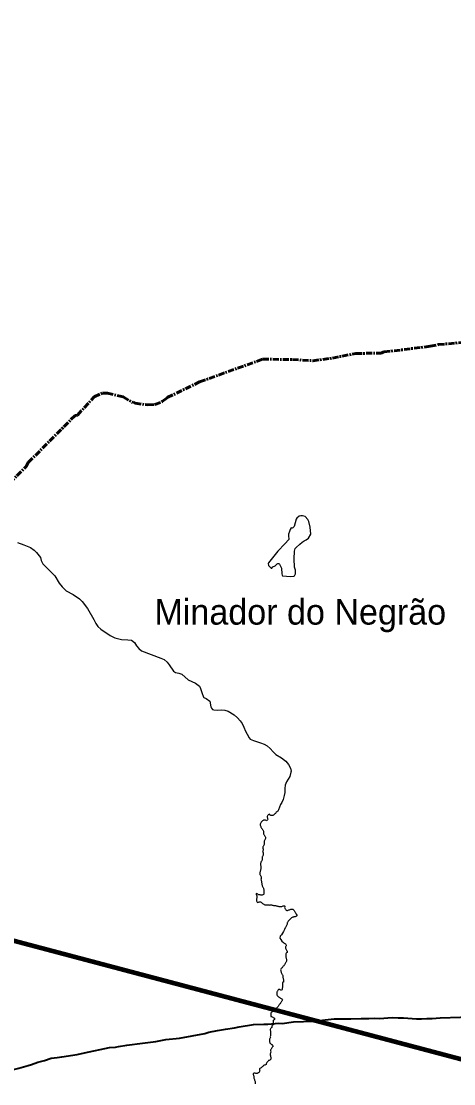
# Model space of a CAD drawing. Extents: x 553962 to 842807, y 8883888 to 9032388.
# Drawn here: x 729266 to 737754, y 8959904 to 8980756 of the extents above; entities that cross this region are included whole.
import ezdxf

# ---------------------------------------------------------------- set-up
doc = ezdxf.new("R2010")
doc.units = 0
doc.header["$LTSCALE"] = 20
doc.linetypes.add('LONG_DASH_SHORT_DASH', pattern=[9.9, 6, -1.2, 1.5, -1.2])
for name, color, linetype, lineweight in [('12', 7, 'Continuous', 25), ('21', 7, 'Continuous', 25), ('24', 7, 'Continuous', 25), ('7', 7, 'LONG_DASH_SHORT_DASH', 60), ('9', 7, 'Continuous', 90)]:
    doc.layers.add(name, color=color, linetype=linetype, lineweight=lineweight)
doc.layers.add('41', color=7, linetype='Continuous')

msp = doc.modelspace()

# ---------------------------------------------------------------- linework, layer by layer
at = {"layer": '12', "lineweight": 40}
for points in [[(734025.23, 8961072.32), (734102.39, 8961075.4), (734319.41, 8961091.81), (734386.94, 8961088.99), (734610.49, 8961116.12), (735000.79, 8961131.4), (735406.19, 8961178.84), (735620.81, 8961178.72)], [(735620.81, 8961178.72), (735731.47, 8961178.65), (735939.14, 8961184.67), (736086.36, 8961182.84), (736197.06, 8961189.1), (736304, 8961187.6), (736462.5, 8961200.24), (736543.42, 8961202.13), (736665.09, 8961195.82), (736768.25, 8961197.31), (737022.4, 8961176.73), (737121.76, 8961176.47), (737224.94, 8961184.42), (737328.09, 8961184.85), (737486.64, 8961197.57), (738285.52, 8961221)], [(731644.16, 8960700.61), (731907.06, 8960733.7), (732104.59, 8960770.61), (732374.96, 8960800.82), (732870.21, 8960888.22), (732949.72, 8960916.31), (733119.64, 8960947.44)], [(733119.64, 8960947.44), (733273.34, 8960975.61), (733450.74, 8961003.08), (733541.83, 8961022.02), (733826.97, 8961064.42), (734025.23, 8961072.32)], [(727488.2, 8960282.3), (728636.39, 8960199.63), (728903.43, 8960161.82), (729137.06, 8960189.26), (729219.73, 8960208.11), (729400.96, 8960258.8), (729465.41, 8960280.38), (729590.56, 8960330.01), (729719.37, 8960362.95), (729852.47, 8960406.02), (729968.99, 8960418.16), (730064.27, 8960434.81), (730362.78, 8960475.91), (730505.92, 8960510.9), (731000.54, 8960614.44), (731116.07, 8960622.55), (731172.08, 8960636.38), (731339.7, 8960662.29), (731644.16, 8960700.61)]]:
    msp.add_lwpolyline(points, dxfattribs=at)
at = {"layer": '21'}
for points in [[(734441.25, 8970498.94), (734303.77, 8970355.74), (734116.51, 8970129.87), (734113.07, 8970114.68), (734119.43, 8970075.48), (734145.25, 8970051.16), (734168.88, 8970019.47), (734181.41, 8970021.52), (734206.5, 8970050.81), (734247.17, 8970065.81), (734290.42, 8970107.38), (734303.52, 8970111.68), (734321.81, 8970111.11), (734333.6, 8970097.89), (734374.96, 8970020.47), (734381.73, 8969909.65), (734389.66, 8969884.17), (734396.24, 8969874.79), (734551.18, 8969860.5), (734613.74, 8969866.7), (734627.41, 8969872.56), (734648.28, 8969912.44), (734649.57, 8969980.8), (734634.29, 8970019.7), (734630.75, 8970039.72), (734623.83, 8970208.99), (734629.39, 8970357.23), (734643.75, 8970405.73), (734658.93, 8970427.23), (734730.63, 8970496.32), (734782.06, 8970530.81), (734817.51, 8970561.34), (734855.16, 8970579.8), (734904.19, 8970611.74), (734951.1, 8970691.29), (734935.85, 8970827.66), (734908.42, 8970936.35), (734891.26, 8970974.5), (734841.32, 8971037.05), (734782.72, 8971051.2)], [(734782.72, 8971051.2), (734756.15, 8971050.77), (734720.75, 8971040.11), (734672.04, 8971001.37), (734663.35, 8970981.58), (734624.87, 8970837.4), (734592.12, 8970806.26), (734562.44, 8970812.01), (734543.57, 8970783.68), (734532.01, 8970740.49), (734512.55, 8970689.17), (734508.82, 8970650.11), (734519.5, 8970599.79), (734514.75, 8970584.31), (734441.25, 8970498.94)]]:
    msp.add_lwpolyline(points, dxfattribs=at)
at = {"layer": '24'}
for points in [[(729191.82, 8970527), (729315.43, 8970483.83), (729446.41, 8970430.03), (729519.73, 8970373.95), (729562.91, 8970331.72), (729643.81, 8970234.41), (729657.78, 8970174.07), (729686.56, 8970110.75), (729928.32, 8969870.5), (730012.38, 8969726.43), (730069.72, 8969653.94), (730149.15, 8969579.47), (730284.77, 8969503.88), (730411.96, 8969418.67), (730463.19, 8969367.61), (730567.65, 8969229.84), (730688.65, 8969016.48), (730730.28, 8968933.73), (730772.23, 8968877.43), (730829.84, 8968823.32), (731008.22, 8968703.56), (731105.33, 8968654.76), (731233.03, 8968624.61), (731360.63, 8968619.29), (731432.16, 8968607.51), (731490.37, 8968564.55), (731529.04, 8968498.91), (731571.99, 8968444.09), (731629.25, 8968401.55), (732006.06, 8968259.5), (732068.71, 8968231.38), (732130.1, 8968177.51), (732172.29, 8968124.3), (732254.14, 8968003.81), (732270.76, 8967986.03), (732292.33, 8967973.47), (732359.39, 8967962.26), (732419.13, 8967940.3), (732541.41, 8967832.4), (732686.56, 8967768.49), (732762.42, 8967705.47), (732787.2, 8967659.88), (732807.75, 8967584.85), (732842.44, 8967493.06), (732851.1, 8967484), (732892.33, 8967462.77), (732967.31, 8967414.94), (732985.96, 8967299.95), (732997.76, 8967278.09), (733022.77, 8967248.47), (733047.48, 8967241.38), (733120.28, 8967238.55), (733188.75, 8967243.53), (733264.7, 8967233.67), (733328.02, 8967214.7), (733447.65, 8967146.11), (733512.9, 8967086.79), (733564.47, 8967027.37), (733599.25, 8966975.33), (733599.25, 8966975.33), (733635.85, 8966903.53)], [(733635.85, 8966903.53), (733667.36, 8966823.62), (733697.18, 8966763.32), (733739.02, 8966694.9), (733760.67, 8966668.39), (733825.78, 8966637.78), (733959.02, 8966591.55), (734034.53, 8966569.68), (734094.57, 8966536.18), (734151.46, 8966484.99), (734209.19, 8966415.67), (734259.55, 8966363.68), (734370.9, 8966301.89), (734433.38, 8966256.02), (734458.56, 8966232.5), (734511.17, 8966171.09), (734552.02, 8966096.35), (734560.3, 8966041.1), (734559.63, 8966020.25), (734537.32, 8965930.66), (734471.1, 8965827.99), (734446.15, 8965764.37), (734439.47, 8965701.01), (734438.02, 8965620.35), (734427.42, 8965560.59), (734408.24, 8965484.42), (734379, 8965420.64), (734356.71, 8965384.15), (734317.42, 8965278.86)], [(734317.42, 8965278.86), (734316.73, 8965277.61), (734309.62, 8965266.03), (734300.35, 8965256.16), (734290.85, 8965247.98), (734280.02, 8965241.51), (734271, 8965232.36), (734262.08, 8965222.25), (734255.22, 8965210.79), (734245.95, 8965201.4), (734235.35, 8965192.38), (734225.24, 8965183.61), (734214.53, 8965176.77), (734203.35, 8965171.15), (734191.09, 8965168.98), (734176.5, 8965168.15), (734165.42, 8965170.52), (734153.34, 8965175.2), (734146.51, 8965187.1), (734135.53, 8965193.7), (734123.74, 8965189.05), (734113.88, 8965181), (734104.73, 8965171.49), (734096.9, 8965160.16), (734091.98, 8965148.45), (734093.83, 8965135.72), (734099.09, 8965124.19), (734101.79, 8965111.22), (734104.37, 8965098.86), (734101.74, 8965086.28), (734094.76, 8965075.07), (734085.26, 8965066.77), (734072.68, 8965069.63), (734061.57, 8965075.87), (734048.74, 8965077.64), (734035.91, 8965079.29), (734022.57, 8965077.8), (734012.94, 8965069.26), (734002.35, 8965061.58), (733992.13, 8965054.25), (733982.61, 8965044.5), (733973.46, 8965035.36), (733966.36, 8965023.78), (733961.19, 8965011.22), (733957.39, 8964996.85), (733956.77, 8964980.05), (733961.69, 8964967.56), (733965.04, 8964954.85), (733969.36, 8964942.73), (733975.5, 8964931.09), (733982.98, 8964920.42), (733992.26, 8964907.19), (733999.86, 8964896.04), (734006.97, 8964885.48), (734014.08, 8964874.69), (734019.13, 8964863.05), (734022.96, 8964850.58), (734021.82, 8964836.9), (734020.57, 8964824.08), (734020.52, 8964810.89), (734024.23, 8964798.66), (734031.22, 8964786.53), (734039.06, 8964776.34), (734045.81, 8964764.7), (734054.25, 8964754.87)], [(734054.25, 8964754.87), (734060.88, 8964743.35), (734062.08, 8964730.86), (734057.13, 8964716.37), (734051.05, 8964704.17), (734044.22, 8964691.97), (734038.96, 8964679.53), (734033.46, 8964667.69), (734031.72, 8964654.38), (734034.22, 8964641.06), (734034.17, 8964628.35), (734034.12, 8964612.98), (734031.65, 8964598.95), (734024.33, 8964586.64), (734018.84, 8964574.67), (734012.73, 8964562.96), (734010.02, 8964550.62), (734009.49, 8964537.92), (734008.96, 8964524.61), (734010.73, 8964510.93), (734016.26, 8964498.56), (734016.58, 8964485.98), (734010.24, 8964474.62), (734004.99, 8964463.27), (734003.85, 8964450.69), (734012.55, 8964441.7), (734016.02, 8964428.62), (734016.21, 8964415.06), (734015.31, 8964401.51), (734012.48, 8964389.18), (734008.19, 8964375.04), (733999.67, 8964365.02), (733992.6, 8964354.15), (733992.8, 8964341.2), (733995.18, 8964328.25), (733996.47, 8964315.29), (733996.06, 8964302.59)], [(733996.06, 8964302.59), (733991.29, 8964290.75), (733985.67, 8964278.42), (733977.03, 8964266.71), (733970.8, 8964254.27), (733966.76, 8964241.94), (733962.84, 8964229.61), (733960.85, 8964216.55), (733959.47, 8964203.97), (733963.67, 8964190.52), (733967.99, 8964177.92), (733970, 8964165.57), (733970.8, 8964152.74), (733969.31, 8964140.28), (733967.8, 8964126.97), (733965.94, 8964114.51), (733963.35, 8964101.82), (733960.16, 8964089.36), (733957.45, 8964076.66), (733954.01, 8964064.33), (733950.21, 8964052), (733949.44, 8964039.42), (733948.78, 8964026.11), (733950.44, 8964013.4), (733956.94, 8964002.36), (733964.9, 8963992.05), (733970.92, 8963980.77), (733975.12, 8963967.21), (733977.13, 8963954.13), (733977.33, 8963941.3), (733974.74, 8963928.48), (733969.85, 8963916.52), (733973.08, 8963904.16), (733975.57, 8963890.97), (733978.07, 8963878.01), (733980.93, 8963864.08), (733983.55, 8963851.73), (733985.69, 8963839.02), (733987.34, 8963825.21), (733990.2, 8963812.98), (733991.37, 8963800.15), (733993.39, 8963787.44), (733998.31, 8963775.92), (734004.45, 8963764.77), (734011.81, 8963753.85), (734019.65, 8963743.9), (734023.12, 8963731.79), (734024.41, 8963718.96), (734025.33, 8963704.31), (734026.37, 8963691.36), (734027.78, 8963677.92), (734028.34, 8963664.85), (734028.29, 8963651.9), (734028.25, 8963639.32), (734025.78, 8963626.98), (734017.26, 8963617.81), (734005.23, 8963608.54), (733993.34, 8963604.58), (733979.77, 8963604.27), (733967.17, 8963605.76), (733955.43, 8963610.64), (733942.46, 8963609.84), (733929.63, 8963614), (733918.5, 8963620.09), (733907.38, 8963627.14)], [(733907.38, 8963627.14), (733896.01, 8963632.63), (733883.9, 8963636.42), (733873.45, 8963628.95), (733873.41, 8963616.13), (733881.86, 8963606.78), (733890.43, 8963597.07), (733892.81, 8963584.48), (733892.76, 8963571.16), (733891.74, 8963557.61), (733888.43, 8963545.16), (733885.23, 8963532.46), (733883.37, 8963519.28), (733883.56, 8963506.21), (733884.61, 8963493.5), (733889.66, 8963481.74), (733897.61, 8963469.86), (733908.25, 8963462.56), (733921.23, 8963465.66), (733932.76, 8963471.79), (733947.19, 8963473.32), (733959.54, 8963471.22), (733971.89, 8963465.61), (733982.89, 8963458.55), (733993.41, 8963451.01), (734003.92, 8963442.63), (734014.32, 8963435.57), (734024.71, 8963427.43), (734036.2, 8963420.01), (734048.67, 8963417.42), (734061.51, 8963417.02), (734075.21, 8963416.73), (734088.54, 8963416.8), (734101.51, 8963418.09), (734115.2, 8963415.26), (734127.43, 8963412.68), (734140.27, 8963411.91)], [(734140.27, 8963411.91), (734153.12, 8963412.47), (734166.69, 8963413.03), (734179.78, 8963412.98), (734192.86, 8963411.36), (734204.72, 8963406.12), (734217.56, 8963403.29), (734230.88, 8963401.79), (734244.94, 8963401.38), (734258.51, 8963399.52), (734272.07, 8963396.45), (734284.66, 8963393.26), (734297.74, 8963389.83), (734309.96, 8963386.4), (734324.62, 8963384.65), (734339.65, 8963384.12), (734353.46, 8963383.71), (734366.55, 8963383.66), (734380.13, 8963384.7), (734392.74, 8963388.29), (734405.85, 8963393.81), (734418.46, 8963396.67), (734431.19, 8963396.63), (734440.98, 8963388.73), (734438.75, 8963376.4), (734433.86, 8963364.43), (734437.21, 8963351.59), (734442.74, 8963339.35), (734449.37, 8963327.71), (734457.2, 8963316.67), (734467.72, 8963309.5), (734480.43, 8963305.46), (734493.4, 8963305.05), (734506.25, 8963307.79), (734517.55, 8963314.17), (734528.96, 8963319.33), (734541.94, 8963323.88), (734554.43, 8963326.99), (734568.63, 8963330.57), (734581.72, 8963331.25), (734594.19, 8963329.27), (734605.32, 8963322.34), (734613.52, 8963312.75), (734620.39, 8963302.07), (734626.41, 8963290.92), (734633.28, 8963280.13), (734640.03, 8963269.09), (734647.26, 8963258.42), (734655.35, 8963248.22), (734662.67, 8963234.65), (734672.77, 8963211.74)], [(734672.77, 8963211.74), (734674.24, 8963206.68), (734674.24, 8963203.58), (734671.79, 8963197.38), (734666.66, 8963191.79), (734656.46, 8963184.57), (734643.96, 8963180.98), (734630.75, 8963180.42), (734617.42, 8963180.46), (734606.25, 8963174.45), (734593.27, 8963171.71), (734581.98, 8963164.97), (734571.05, 8963158.36), (734560.23, 8963150.04), (734550.02, 8963141.12), (734540.66, 8963132.2), (734531.65, 8963121.82), (734523.25, 8963111.81), (734513.65, 8963102.28), (734503.32, 8963094.33), (734495.16, 8963084.56), (734491.48, 8963070.65), (734487.32, 8963058.81), (734483.76, 8963046.6), (734481.77, 8963033.41), (734475.79, 8963021.33), (734469.09, 8963009.98), (734463.71, 8962997.89), (734452.35, 8962973.09)], [(734452.35, 8962973.09), (734447.59, 8962962.36), (734429.68, 8962928.51), (734414.17, 8962893.93), (734396.5, 8962860.8), (734373.91, 8962829.77), (734350.61, 8962800.07), (734340.39, 8962763.39), (734361.58, 8962732.11), (734382.75, 8962699.14), (734411.47, 8962673.7), (734426.34, 8962663.57), (734439.78, 8962656.95), (734450.09, 8962649.51), (734460.71, 8962637.12), (734463.73, 8962623.84), (734462.29, 8962611.19), (734455.92, 8962600.03), (734451.71, 8962588.5), (734451.6, 8962576.2), (734454.63, 8962563.76), (734460.67, 8962551.29), (734465.99, 8962539.43), (734473.24, 8962527.68), (734480.48, 8962515.08), (734485.32, 8962503.22), (734487.38, 8962490.19), (734483.66, 8962478.65), (734472.87, 8962472.47), (734463.86, 8962463.62), (734460.86, 8962451.83), (734460.87, 8962439.42), (734460.75, 8962426.16), (734458.81, 8962411.35), (734458.09, 8962398.45), (734460.03, 8962386.5), (734462.58, 8962374.67), (734466.57, 8962362.58), (734470.81, 8962350.73), (734471.66, 8962337.7), (734471.52, 8962322.51), (734471.28, 8962308.89), (734467.44, 8962297.23), (734460.83, 8962286.32), (734455.3, 8962275.4), (734448.8, 8962263.15), (734440.97, 8962251.41), (734433.16, 8962240.74), (734425.21, 8962229), (734417.41, 8962219.06), (734409.11, 8962209), (734399.98, 8962199.07), (734391.7, 8962189.98), (734383.66, 8962181), (734374.18, 8962173.13), (734366.02, 8962164.28), (734357.84, 8962153.62), (734354.83, 8962140.98), (734357.82, 8962123.96), (734360.12, 8962112.01), (734364.45, 8962097.38), (734370.5, 8962085.52), (734375.33, 8962073.54), (734380.06, 8962061.93), (734387.19, 8962050.9), (734392.88, 8962039.64), (734398.08, 8962027.3), (734401.71, 8962015.22), (734402.32, 8962002.19), (734402.44, 8961989.41), (734404.14, 8961976.59), (734406.81, 8961963.06), (734410.79, 8961952.45), (734414.05, 8961938.92), (734414.17, 8961925.18), (734413.81, 8961912.28), (734411.41, 8961900.01), (734399.91, 8961895.89), (734394.75, 8961884.96), (734391.51, 8961872.93), (734391.24, 8961870.4), (734391.11, 8961855.7), (734390.98, 8961841.35), (734390.88, 8961829.3), (734390.76, 8961816.64), (734390.65, 8961803.86), (734390.29, 8961790.97), (734390.06, 8961778.55), (734389.95, 8961766.5), (734388.03, 8961754.46), (734380.71, 8961744.27), (734370.98, 8961736.16), (734358.22, 8961738.07), (734350.1, 8961747.3), (734338.69, 8961752.7), (734327.02, 8961755.82), (734315.06, 8961754.35), (734307.73, 8961744.04), (734302.09, 8961733.36), (734296.44, 8961722.2), (734289.23, 8961711.29)], [(734289.23, 8961711.29), (734283.82, 8961700), (734281.54, 8961688.09), (734280.94, 8961674.59), (734280.82, 8961661.57), (734284.7, 8961649.73), (734287.36, 8961637.41), (734296.44, 8961627.45), (734306.73, 8961619.04), (734316.07, 8961610.77), (734326.25, 8961603.09), (734335.96, 8961596.01), (734346.75, 8961589.65), (734356.94, 8961581.97), (734368.82, 8961575.48), (734379.86, 8961568.88), (734388.58, 8961559.89), (734395.61, 8961549.82), (734388.5, 8961537.7), (734380.45, 8961527.41), (734372.77, 8961518.07), (734365.56, 8961507.4), (734359.42, 8961496), (734352.21, 8961485.45), (734344.51, 8961473.58), (734337.43, 8961463.88), (734328.9, 8961454.06), (734321.44, 8961443.15), (734314.95, 8961432.6), (734307.37, 8961421.21), (734299.32, 8961410.67), (734290.79, 8961400.62), (734280.69, 8961391.06), (734271.07, 8961380.77), (734263.03, 8961371.56), (734254.02, 8961362.11), (734242.97, 8961354.37), (734232.17, 8961347.1), (734222.1, 8961340.44), (734211.79, 8961333.77), (734200.99, 8961326.99), (734191.39, 8961318.15), (734182.86, 8961308.7), (734173.38, 8961301.07), (734167.02, 8961290.75), (734166.79, 8961278.58), (734166.68, 8961265.92), (734166.43, 8961252.42), (734165.83, 8961238.44), (734167.29, 8961226.5), (734178.34, 8961221.34), (734190.97, 8961218.22), (734202.86, 8961212.09), (734213.04, 8961204.53), (734223.83, 8961197.45), (734234.27, 8961191.33), (734239.36, 8961180.2), (734236.84, 8961167.93), (734227.71, 8961158.72), (734219.56, 8961150.84), (734213.23, 8961144.34), (734207.2, 8961131.53), (734207.93, 8961118.26), (734211.44, 8961106.18), (734218.02, 8961091.06)], [(734218.02, 8961091.06), (734207.79, 8961062.93), (734199.99, 8961052.99), (734190.86, 8961044.15), (734184.62, 8961033.59), (734182.58, 8961021.31), (734181.74, 8961009.26), (734171.79, 8961001.75), (734165.3, 8960991.32), (734157.61, 8960980.9), (734153.4, 8960969.12), (734153.9, 8960956.94), (734155.72, 8960944.75), (734155.59, 8960930.76), (734157.17, 8960918.57), (734157.28, 8960903.75), (734157.41, 8960891.57), (734158.58, 8960889.53), (734158.73, 8960875.59), (734155.38, 8960860.06), (734154.83, 8960846.84), (734154.51, 8960832.86), (734154.72, 8960820.12), (734151.44, 8960807.71), (734146.52, 8960794.58), (734140.09, 8960780.86), (734140.04, 8960767.76), (734139.74, 8960754.78), (734139.41, 8960740.18), (734140.37, 8960727.18), (734143.21, 8960714.88), (734147.92, 8960702.17), (734155.28, 8960690.65), (734166.26, 8960684.68), (734176.84, 8960677.46), (734187.82, 8960671.36), (734189.29, 8960669.76)], [(734189.29, 8960669.76), (734197.09, 8960661.3), (734205.74, 8960651.87), (734207.83, 8960639.22), (734198.62, 8960629.55), (734192.37, 8960618.58), (734185.63, 8960607.74), (734178.12, 8960596.16), (734172.62, 8960584.92), (734163.43, 8960576.38), (734155.81, 8960565.43), (734158.65, 8960553.01), (734164.26, 8960541.4), (734158.59, 8960528.29), (734163.68, 8960516.2), (734160.77, 8960503.15), (734153.04, 8960492.96), (734150.53, 8960481.38), (734151.26, 8960469.9), (734157.4, 8960454.04), (734161.11, 8960441.48), (734162.31, 8960428.09), (734164.26, 8960415.07), (734164.47, 8960402.2), (734163.06, 8960389.5), (734158.16, 8960377.62), (734150.69, 8960367.42), (734141.73, 8960366.87), (734131.76, 8960362.72), (734121.76, 8960358.93), (734113.76, 8960347.74), (734103.8, 8960338.34), (734094.23, 8960329.3), (734087.12, 8960318.72), (734080.86, 8960307.37), (734075.35, 8960295.5), (734070.08, 8960283.88), (734057.82, 8960277.4), (734046.23, 8960267.91), (734033.33, 8960266.19), (734022.56, 8960259.81), (734013.08, 8960249.4), (734003.4, 8960240.99), (733993.22, 8960232.97), (733983.65, 8960224.06), (733973.49, 8960216.66), (733963.19, 8960208.89), (733950.49, 8960205.42), (733944.1, 8960193.45), (733941.56, 8960180.52), (733944.13, 8960167.23), (733946.97, 8960154.94), (733945.06, 8960142.12), (733938.63, 8960128.77), (733928.59, 8960120.87), (733915.49, 8960116.29), (733904.7, 8960108.65), (733893.31, 8960102.28), (733880.09, 8960103.44), (733866.8, 8960106.59), (733854.78, 8960110.97), (733841.67, 8960111.37), (733828.27, 8960110.04), (733814.94, 8960100.84), (733814.49, 8960086.36)], [(733814.49, 8960086.36), (733821.22, 8960074.73), (733825.57, 8960062.78), (733828.54, 8960050.23), (733828.24, 8960037.13), (733829.81, 8960023.74), (733832.03, 8960011.33), (733837.21, 8959997.62), (733842.31, 8959985.52), (733846.4, 8959973.33), (733851.25, 8959961.11), (733856.65, 8959946.02), (733856.47, 8959932.66), (733859.67, 8959919.36), (733860.17, 8959902.87)]]:
    msp.add_lwpolyline(points, dxfattribs=at)
msp.add_spline([(715037.02, 8973071.84), (715705.05, 8973746.18), (715968.52, 8974273.46), (716313.06, 8974881.86), (716799.47, 8975226.62), (717083.21, 8975429.42), (717285.88, 8975328.02), (717752.02, 8975003.54), (717934.43, 8974821.02), (718137.1, 8974800.74), (718522.17, 8975145.5), (718826.18, 8975165.78), (718927.51, 8975307.74), (719251.79, 8975287.46), (719596.33, 8975855.3), (719799, 8976301.46), (720042.2, 8976686.78), (720771.82, 8977072.1), (721197.43, 8977051.82), (721481.16, 8977356.02), (721987.84, 8977396.58), (722291.85, 8977356.02), (722514.78, 8977639.94), (722859.32, 8978086.1), (723244.4, 8978309.18), (723548.4, 8978795.9), (723507.87, 8979566.54), (723426.8, 8979749.06), (723730.81, 8980235.77), (724115.88, 8980418.29), (724500.96, 8980803.61), (724886.03, 8981067.25), (724886.03, 8981594.53), (724865.76, 8981939.29), (725068.43, 8982385.45), (725169.76, 8982831.61), (725331.9, 8983216.93), (725311.63, 8983581.97), (725473.77, 8983825.33), (725696.71, 8983987.57), (725777.78, 8984433.73), (725858.84, 8984636.53), (726183.12, 8984636.53), (726162.85, 8984920.45), (726284.45, 8985163.81), (726588.46, 8985569.41), (726993.8, 8986056.13), (726770.86, 8986299.49), (726466.86, 8986238.65), (726264.19, 8986340.05), (726527.66, 8986563.13), (726487.12, 8986745.65), (726770.86, 8986907.89), (727155.94, 8987090.41), (727297.81, 8987171.53), (727338.34, 8987496.01), (727581.55, 8987698.81), (727743.68, 8987921.89), (727905.82, 8988084.13), (728067.95, 8988408.6), (728351.69, 8988510), (728453.03, 8988814.2), (728655.7, 8988854.76), (728675.97, 8989098.12), (728898.9, 8989260.36), (729121.84, 8989260.36), (729283.98, 8989037.28), (729527.18, 8988733.08), (729750.12, 8988712.8), (729973.06, 8988834.48), (729993.33, 8988753.36), (730054.13, 8988530.28), (730135.2, 8988469.44), (730358.13, 8988469.44), (730459.47, 8988408.6), (730702.67, 8988489.72), (730702.67, 8988611.4), (730885.08, 8988651.96), (731067.48, 8988469.44), (731168.82, 8988347.76), (731472.82, 8988368.04), (731736.29, 8988631.68), (731857.9, 8988834.48), (732222.69, 8988814.2), (732324.03, 8989017), (732506.43, 8989138.68), (732546.97, 8989300.92), (732850.97, 8989402.32), (733073.91, 8989382.04), (733114.44, 8989665.96), (733215.78, 8989848.48)], degree=3, dxfattribs=at)
at = {"layer": '7'}
msp.add_lwpolyline([(729041.36, 8971697.76), (729364.52, 8972018.14), (729404.2, 8972096.7), (730321.7, 8973018.85), (730368.36, 8973026.01), (730699.36, 8973383.64), (730862.04, 8973459.92), (730956.1, 8973459.96), (731265.79, 8973385.6), (731447.76, 8973274.4), (731473.56, 8973278.49), (731501.8, 8973259.3), (731752.08, 8973224.93), (731885.37, 8973232.76), (732033.34, 8973290.93), (732132.69, 8973369.83), (732767.6, 8973679.24), (734004.36, 8974123.58), (734587.51, 8974117.08), (734986.26, 8974093.78), (735372.69, 8974147.22), (735835.38, 8974235.08), (736327.37, 8974244.94), (736385.28, 8974265.19), (737292.22, 8974376.72), (737450.94, 8974411), (738250.69, 8974481.49)], dxfattribs=at)
at = {"layer": '9'}
msp.add_line((738230.17, 8960292.86), (727062.75, 8963254.11), dxfattribs=at)

# ---------------------------------------------------------------- texts
at = {"layer": '41'}
msp.add_text('Minador do Negrão', height=500, dxfattribs=at).set_placement((731880.74, 8968914.64))

doc.saveas('drawing.dxf')
